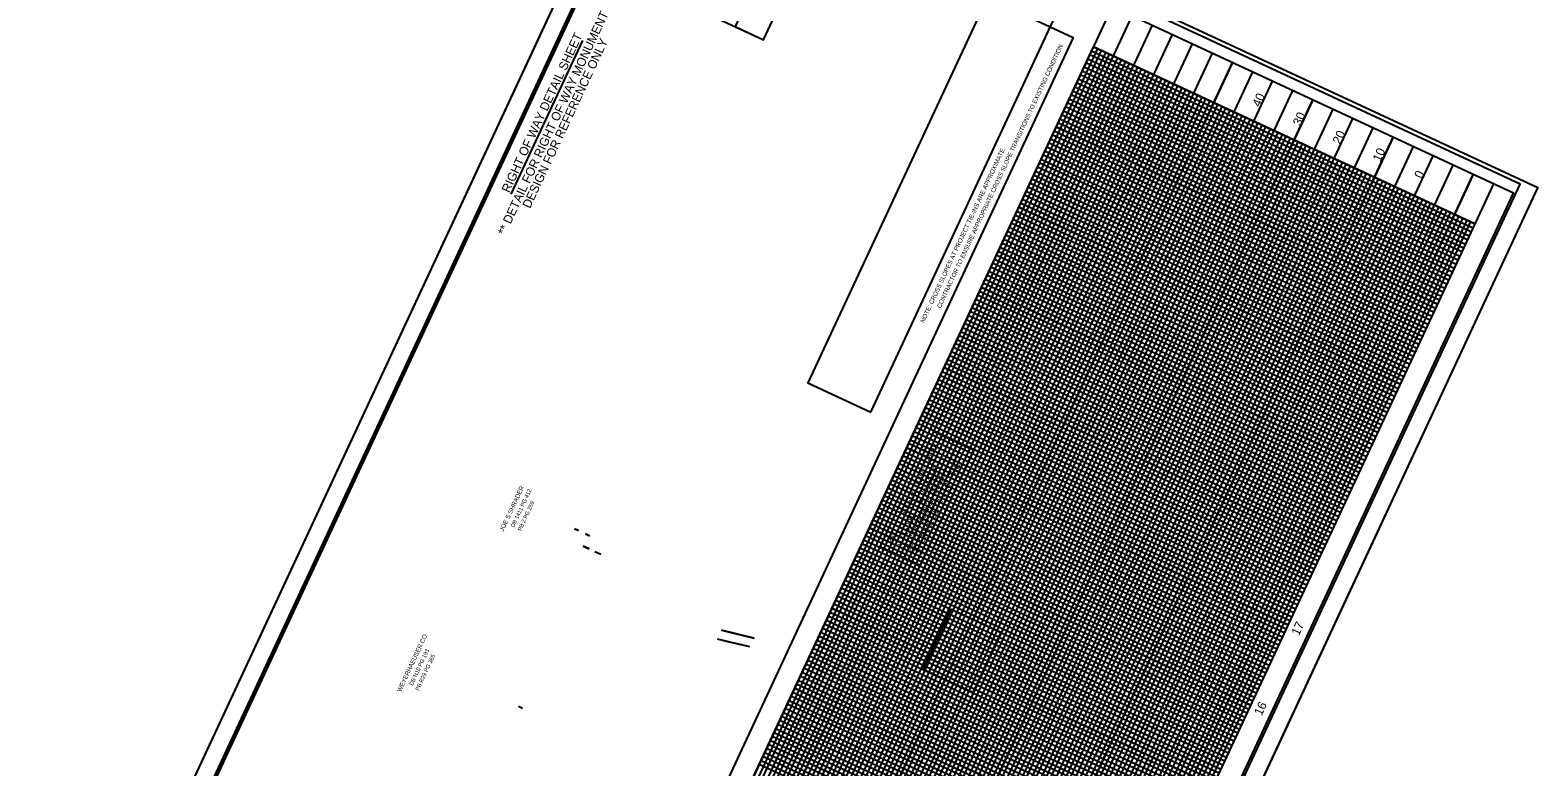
# Model space of a CAD drawing. Extents: x 2532214 to 2533961, y 714631 to 717266.
# Drawn here: x 2532214 to 2533917, y 715503 to 716336 of the extents above; entities that cross this region are included whole.
import ezdxf

# ---------------------------------------------------------------- set-up
doc = ezdxf.new("R2010")
doc.units = 0
for name, color, linetype in [('Default', 7, 'Continuous'), ('Exist Vertical Profile Horizontal Axis Label Major', 7, 'Continuous'), ('Exist Vertical Profile Vertical Axis Label', 7, 'Continuous'), ('Old_Level_1', 7, 'Continuous'), ('Prop Dimension Text', 7, 'Continuous'), ('Raster_Level_0', 7, 'Continuous'), ('Scratch_Level_0', 7, 'Continuous'), ('Scratch_Level_3', 7, 'Continuous'), ('Sheet Cutting Line CELL', 7, 'Continuous'), ('Sheet Data Field CELL', 7, 'Continuous'), ('Sheet DOT Grid CELL', 7, 'Continuous'), ('Sheet Layout Plan Border', 7, 'Continuous'), ('Sheet Plan And Profile CELL', 7, 'Continuous'), ('Sheet Plot Border Inside CELL', 7, 'Continuous'), ('Sheet Plot Border Outside CELL', 7, 'Continuous'), ('Sheet Profile Grid Major CELL', 7, 'Continuous'), ('Sheet Profile Grid Middle CELL', 7, 'Continuous'), ('Sheet Profile Grid Minor CELL', 7, 'Continuous'), ('Sheet Typical CELL', 7, 'Continuous')]:
    doc.layers.add(name, color=color, linetype=linetype)

msp = doc.modelspace()

# ---------------------------------------------------------------- linework, layer by layer
at = {"layer": 'Default'}
for points in [[(2533174.3, 715751.9), (2533235, 715882.3), (2533280.2, 715861.3), (2533219.5, 715730.8)], [(2533174.3, 715751.9), (2533235, 715882.3), (2533280.2, 715861.3), (2533219.5, 715730.8)], [(2533222.8, 715613.4), (2533254.5, 715681.4), (2533310.4, 715655.4), (2533278.8, 715587.4)], [(2533222.8, 715613.4), (2533254.5, 715681.4), (2533310.4, 715655.4), (2533278.8, 715587.4)]]:
    msp.add_lwpolyline(points, close=True, dxfattribs=at)
at = {"layer": 'Old_Level_1'}
for p, q in [((2532833.6, 715770.3), (2532829.1, 715772.4)), ((2532838.9, 715752.7), (2532845.7, 715749.6)), ((2532846, 715764.5), (2532841.4, 715766.7)), ((2532994.9, 715657.6), (2533005.6, 715655.1)), ((2533005.6, 715655.1), (2533031.8, 715648.8)), ((2532990.2, 715647.8), (2533001.9, 715645)), ((2533001.9, 715645), (2533026.7, 715639.1))]:
    msp.add_line(p, q, dxfattribs=at)
at = {"layer": 'Raster_Level_0'}
for p, q in [((2532829.1, 715772.4), (2532833.6, 715770.3)), ((2532845.7, 715749.6), (2532838.9, 715752.7)), ((2532841.4, 715766.7), (2532846, 715764.5)), ((2532851.8, 715746.7), (2532858.6, 715743.6)), ((2533031.8, 715648.8), (2532994.9, 715657.6)), ((2532990.2, 715647.8), (2533026.7, 715639.1)), ((2532765.6, 715571.8), (2532770.1, 715569.6))]:
    msp.add_line(p, q, dxfattribs=at)
msp.add_lwpolyline([(2533163.7, 715904.1), (2533382.1, 716373.6), (2533311, 716406.7), (2533092.5, 715937.2)], close=True, dxfattribs=at)
at = {"layer": 'Scratch_Level_0'}
msp.add_lwpolyline([(2532325.9, 715280), (2532853.1, 716413.3), (2533042.4, 716325.3), (2533126.8, 716506.7), (2533345.5, 716404.9), (2533436.2, 716362.7), (2533229.5, 715918.4), (2532824.5, 715048)], close=True, dxfattribs=at)
at = {"layer": 'Scratch_Level_3'}
msp.add_lwpolyline([(2532824.5, 715048), (2533229.5, 715918.4), (2533415.1, 716317.4), (2533539.1, 716259.7), (2533845.8, 716117), (2533255.2, 714847.7)], close=True, dxfattribs=at)
at = {"layer": 'Sheet Cutting Line CELL'}
for p, q in [((2532924.3, 716619.6), (2532214.1, 715093.2)), ((2533206.9, 714631.3), (2533917.1, 716157.7))]:
    msp.add_line(p, q, dxfattribs=at)
at = {"layer": 'Sheet Data Field CELL'}
msp.add_line((2532757.5, 716150.5), (2532838.3, 716324.3), dxfattribs=at)
at = {"layer": 'Sheet DOT Grid CELL'}
for p, q in [((2532939.4, 714939.4), (2533572.2, 716299.4)), ((2532848.8, 714981.6), (2533460.4, 716296.3)), ((2532894.1, 714960.5), (2533505.8, 716275.2)), ((2532984.8, 714918.3), (2533617.5, 716278.3)), ((2533394, 716272), (2533824.7, 716071.7)), ((2533030.1, 714897.2), (2533662.9, 716257.2)), ((2533075.4, 714876.1), (2533708.2, 716236.2)), ((2533120.8, 714855), (2533753.5, 716215.1)), ((2533372.9, 716226.7), (2533803.6, 716026.3)), ((2533166.1, 714834), (2533798.9, 716194)), ((2533351.8, 716181.4), (2533782.5, 715981)), ((2533211.4, 714812.9), (2533844.2, 716172.9)), ((2533330.7, 716136), (2533761.4, 715935.7)), ((2533309.6, 716090.7), (2533740.3, 715890.3)), ((2533288.5, 716045.4), (2533719.2, 715845)), ((2533267.5, 716000), (2533698.1, 715799.7)), ((2533246.4, 715954.7), (2533677, 715754.3)), ((2533225.3, 715909.4), (2533655.9, 715709)), ((2533204.2, 715864), (2533634.8, 715663.7)), ((2533183.1, 715818.7), (2533613.8, 715618.3)), ((2533162, 715773.4), (2533592.7, 715573)), ((2533140.9, 715728), (2533571.6, 715527.7)), ((2533119.8, 715682.7), (2533550.5, 715482.3)), ((2533098.7, 715637.4), (2533529.4, 715437)), ((2533077.6, 715592), (2533508.3, 715391.7)), ((2533056.5, 715546.7), (2533487.2, 715346.3))]:
    msp.add_line(p, q, dxfattribs=at)
at = {"layer": 'Sheet Layout Plan Border'}
msp.add_lwpolyline([(2532801.9, 715058.6), (2532325.9, 715280), (2532853.1, 716413.3), (2533042.4, 716325.3), (2533105.7, 716461.3), (2533392.4, 716327.9)], close=True, dxfattribs=at)
at = {"layer": 'Sheet Plan And Profile CELL'}
for p, q in [((2533436.2, 716362.7), (2532803.4, 715002.7)), ((2533866.9, 716162.3), (2533234.1, 714802.3))]:
    msp.add_line(p, q, dxfattribs=at)
msp.add_lwpolyline([(2532937.5, 716594.7), (2532304.8, 715234.7), (2533256.8, 714791.8), (2533889.5, 716151.8)], close=True, dxfattribs=at)
at = {"layer": 'Sheet Plot Border Inside CELL'}
msp.add_lwpolyline([(2533194.3, 714651.5), (2533897.1, 716162.1), (2532940.5, 716607.1), (2532237.8, 715096.6)], close=True, dxfattribs=at)
at = {"layer": 'Sheet Plot Border Outside CELL'}
msp.add_lwpolyline([(2533206.9, 714631.3), (2533917.1, 716157.7), (2532924.3, 716619.6), (2532214.1, 715093.2)], close=True, dxfattribs=at)
at = {"layer": 'Sheet Profile Grid Major CELL'}
for p, q in [((2533481.5, 716341.6), (2532848.8, 714981.6)), ((2532894.1, 714960.5), (2533526.9, 716320.5)), ((2533845.8, 716117), (2533415.1, 716317.4)), ((2533572.2, 716299.4), (2532939.4, 714939.4)), ((2532984.8, 714918.3), (2533617.5, 716278.3)), ((2533394, 716272), (2533824.7, 716071.7)), ((2533662.9, 716257.2), (2533030.1, 714897.2)), ((2533075.4, 714876.1), (2533708.2, 716236.2)), ((2533753.5, 716215.1), (2533120.8, 714855)), ((2533803.6, 716026.3), (2533372.9, 716226.7)), ((2533166.1, 714834), (2533798.9, 716194)), ((2533351.8, 716181.4), (2533782.5, 715981)), ((2533844.2, 716172.9), (2533211.4, 714812.9)), ((2533761.4, 715935.7), (2533330.7, 716136)), ((2533309.6, 716090.7), (2533740.3, 715890.3)), ((2533719.2, 715845), (2533288.5, 716045.4)), ((2533267.5, 716000), (2533698.1, 715799.7)), ((2533677, 715754.3), (2533246.4, 715954.7)), ((2533225.3, 715909.4), (2533655.9, 715709)), ((2533634.8, 715663.7), (2533204.2, 715864)), ((2533183.1, 715818.7), (2533613.8, 715618.3)), ((2533592.7, 715573), (2533162, 715773.4)), ((2533140.9, 715728), (2533571.6, 715527.7)), ((2533550.5, 715482.3), (2533119.8, 715682.7)), ((2533098.7, 715637.4), (2533529.4, 715437)), ((2533508.3, 715391.7), (2533077.6, 715592)), ((2533056.5, 715546.7), (2533487.2, 715346.3))]:
    msp.add_line(p, q, dxfattribs=at)
at = {"layer": 'Sheet Profile Grid Middle CELL'}
for p, q in [((2532826.1, 714992.1), (2533458.9, 716352.2)), ((2533504.2, 716331.1), (2532871.4, 714971.1)), ((2532916.8, 714950), (2533549.5, 716310)), ((2533594.9, 716288.9), (2532962.1, 714928.9)), ((2533404.5, 716294.7), (2533835.2, 716094.3)), ((2533007.4, 714907.8), (2533640.2, 716267.8)), ((2533685.5, 716246.7), (2533052.8, 714886.7)), ((2533814.1, 716049), (2533383.5, 716249.4)), ((2533098.1, 714865.6), (2533730.9, 716225.6)), ((2533776.2, 716204.5), (2533143.4, 714844.5)), ((2533362.4, 716204), (2533793, 716003.7)), ((2533188.8, 714823.4), (2533821.5, 716183.4)), ((2533771.9, 715958.3), (2533341.3, 716158.7)), ((2533320.2, 716113.4), (2533750.9, 715913)), ((2533729.8, 715867.7), (2533299.1, 716068)), ((2533278, 716022.7), (2533708.7, 715822.3)), ((2533687.6, 715777), (2533256.9, 715977.4)), ((2533235.8, 715932), (2533666.5, 715731.7)), ((2533645.4, 715686.3), (2533214.7, 715886.7)), ((2533193.6, 715841.4), (2533624.3, 715641)), ((2533603.2, 715595.7), (2533172.5, 715796)), ((2533151.5, 715750.7), (2533582.1, 715550.3)), ((2533561, 715505), (2533130.4, 715705.4)), ((2533109.3, 715660), (2533539.9, 715459.7)), ((2533518.8, 715414.3), (2533088.2, 715614.7)), ((2533067.1, 715569.4), (2533497.8, 715369)), ((2533476.7, 715323.7), (2533046, 715524))]:
    msp.add_line(p, q, dxfattribs=at)
at = {"layer": 'Sheet Profile Grid Minor CELL'}
for p, q in [((2533419.6, 716315.3), (2532829.1, 715045.9)), ((2532833.6, 715043.8), (2533424.2, 716313.2)), ((2533428.7, 716311), (2532838.1, 715041.7)), ((2532842.7, 715039.6), (2533433.2, 716308.9)), ((2533442.3, 716304.7), (2532851.7, 715035.4)), ((2532856.3, 715033.3), (2533446.8, 716302.6)), ((2533451.4, 716300.5), (2532860.8, 715031.1)), ((2532865.3, 715029), (2533455.9, 716298.4)), ((2533837.3, 716098.9), (2533406.7, 716299.2)), ((2533408.8, 716303.8), (2533839.4, 716103.4)), ((2533841.5, 716107.9), (2533410.9, 716308.3)), ((2533413, 716312.8), (2533843.7, 716112.5)), ((2533465, 716294.2), (2532874.4, 715024.8)), ((2532878.9, 715022.7), (2533469.5, 716292.1)), ((2533474, 716289.9), (2532883.5, 715020.6)), ((2532888, 715018.5), (2533478.6, 716287.8)), ((2533487.6, 716283.6), (2532897.1, 715014.3)), ((2532901.6, 715012.2), (2533492.2, 716281.5)), ((2533398.2, 716281.1), (2533828.9, 716080.7)), ((2533831, 716085.3), (2533400.3, 716285.6)), ((2533402.4, 716290.2), (2533833.1, 716089.8)), ((2533496.7, 716279.4), (2532906.1, 715010.1)), ((2532910.7, 715007.9), (2533501.2, 716277.3)), ((2532919.7, 715003.7), (2533510.3, 716273.1)), ((2533514.8, 716271), (2532924.3, 715001.6)), ((2532928.8, 714999.5), (2533519.4, 716268.9)), ((2533523.9, 716266.7), (2532933.3, 714997.4)), ((2533391.9, 716267.5), (2533822.6, 716067.1)), ((2533826.8, 716076.2), (2533396.1, 716276.6)), ((2532942.4, 714993.2), (2533533, 716262.5)), ((2533537.5, 716260.4), (2532946.9, 714991.1)), ((2532951.5, 714989), (2533542, 716258.3)), ((2533546.6, 716256.2), (2532956, 714986.9)), ((2532965.1, 714982.6), (2533555.6, 716252)), ((2533560.2, 716249.9), (2532969.6, 714980.5)), ((2532974.1, 714978.4), (2533564.7, 716247.8)), ((2533816.2, 716053.5), (2533385.6, 716253.9)), ((2533387.7, 716258.4), (2533818.3, 716058.1)), ((2533820.5, 716062.6), (2533389.8, 716263)), ((2533569.2, 716245.7), (2532978.7, 714976.3)), ((2532987.7, 714972.1), (2533578.3, 716241.4)), ((2533582.8, 716239.3), (2532992.3, 714970)), ((2532996.8, 714967.9), (2533587.4, 716237.2)), ((2533591.9, 716235.1), (2533001.3, 714965.8)), ((2533010.4, 714961.5), (2533601, 716230.9)), ((2533805.7, 716030.9), (2533375, 716231.2)), ((2533377.1, 716235.8), (2533807.8, 716035.4)), ((2533809.9, 716039.9), (2533379.2, 716240.3)), ((2533381.3, 716244.8), (2533812, 716044.5)), ((2533605.5, 716228.8), (2533014.9, 714959.4)), ((2533019.5, 714957.3), (2533610, 716226.7)), ((2533614.6, 716224.6), (2533024, 714955.2)), ((2533033.1, 714951), (2533623.6, 716220.3)), ((2533628.2, 716218.2), (2533037.6, 714948.9)), ((2533042.1, 714946.8), (2533632.7, 716216.1)), ((2533637.2, 716214), (2533046.7, 714944.7)), ((2533366.6, 716213.1), (2533797.3, 716012.7)), ((2533799.4, 716017.3), (2533368.7, 716217.6)), ((2533370.8, 716222.2), (2533801.5, 716021.8)), ((2533055.7, 714940.5), (2533646.3, 716209.8)), ((2533650.8, 716207.7), (2533060.3, 714938.3)), ((2533064.8, 714936.2), (2533655.4, 716205.6)), ((2533659.9, 716203.5), (2533069.3, 714934.1)), ((2533078.4, 714929.9), (2533669, 716199.3)), ((2533673.5, 716197.1), (2533082.9, 714927.8)), ((2533360.3, 716199.5), (2533790.9, 715999.1)), ((2533795.1, 716008.2), (2533364.5, 716208.6)), ((2533087.5, 714925.7), (2533678, 716195)), ((2533682.6, 716192.9), (2533092, 714923.6)), ((2533101.1, 714919.4), (2533691.6, 716188.7)), ((2533696.2, 716186.6), (2533105.6, 714917.3)), ((2533110.1, 714915.1), (2533700.7, 716184.5)), ((2533705.2, 716182.4), (2533114.7, 714913)), ((2533784.6, 715985.5), (2533353.9, 716185.9)), ((2533356, 716190.4), (2533786.7, 715990.1)), ((2533788.8, 715994.6), (2533358.1, 716195)), ((2533123.7, 714908.8), (2533714.3, 716178.2)), ((2533718.8, 716176.1), (2533128.3, 714906.7)), ((2533132.8, 714904.6), (2533723.4, 716173.9)), ((2533727.9, 716171.8), (2533137.3, 714902.5)), ((2533146.4, 714898.3), (2533737, 716167.6)), ((2533741.5, 716165.5), (2533150.9, 714896.2)), ((2533155.5, 714894.1), (2533746, 716163.4)), ((2533774.1, 715962.9), (2533343.4, 716163.2)), ((2533345.5, 716167.8), (2533776.2, 715967.4)), ((2533778.3, 715971.9), (2533347.6, 716172.3)), ((2533349.7, 716176.8), (2533780.4, 715976.5)), ((2533750.6, 716161.3), (2533160, 714891.9)), ((2533169.1, 714887.7), (2533759.6, 716157.1)), ((2533764.2, 716155), (2533173.6, 714885.6)), ((2533178.1, 714883.5), (2533768.7, 716152.9)), ((2533773.2, 716150.7), (2533182.7, 714881.4)), ((2533191.7, 714877.2), (2533782.3, 716146.5)), ((2533196.3, 714875.1), (2533786.8, 716144.4)), ((2533334.9, 716145.1), (2533765.6, 715944.7)), ((2533767.7, 715949.3), (2533337.1, 716149.6)), ((2533339.2, 716154.2), (2533769.8, 715953.8)), ((2533791.4, 716142.3), (2533200.8, 714873)), ((2533205.3, 714870.9), (2533795.9, 716140.2)), ((2533805, 716136), (2533214.4, 714866.6)), ((2533218.9, 714864.5), (2533809.5, 716133.9)), ((2533814, 716131.8), (2533223.5, 714862.4)), ((2533228, 714860.3), (2533818.6, 716129.7)), ((2533328.6, 716131.5), (2533759.3, 715931.1)), ((2533763.5, 715940.2), (2533332.8, 716140.6)), ((2533827.6, 716125.4), (2533237.1, 714856.1)), ((2533241.6, 714854), (2533832.2, 716123.3)), ((2533836.7, 716121.2), (2533246.1, 714851.9)), ((2533250.7, 714849.8), (2533841.2, 716119.1)), ((2533753, 715917.5), (2533322.3, 716117.9)), ((2533324.4, 716122.4), (2533755.1, 715922.1)), ((2533757.2, 715926.6), (2533326.5, 716127)), ((2533742.4, 715894.9), (2533311.7, 716095.2)), ((2533313.9, 716099.8), (2533744.5, 715899.4)), ((2533746.6, 715903.9), (2533316, 716104.3)), ((2533318.1, 716108.8), (2533748.7, 715908.5)), ((2533303.3, 716077.1), (2533734, 715876.7)), ((2533736.1, 715881.3), (2533305.4, 716081.6)), ((2533307.5, 716086.2), (2533738.2, 715885.8)), ((2533297, 716063.5), (2533727.7, 715863.1)), ((2533731.9, 715872.2), (2533301.2, 716072.6)), ((2533721.3, 715849.5), (2533290.7, 716049.9)), ((2533292.8, 716054.4), (2533723.4, 715854.1)), ((2533725.5, 715858.6), (2533294.9, 716059)), ((2533710.8, 715826.9), (2533280.1, 716027.2)), ((2533282.2, 716031.8), (2533712.9, 715831.4)), ((2533715, 715835.9), (2533284.3, 716036.3)), ((2533286.4, 716040.8), (2533717.1, 715840.5)), ((2533271.7, 716009.1), (2533702.3, 715808.7)), ((2533704.5, 715813.3), (2533273.8, 716013.6)), ((2533275.9, 716018.2), (2533706.6, 715817.8)), ((2533265.3, 715995.5), (2533696, 715795.1)), ((2533700.2, 715804.2), (2533269.6, 716004.6)), ((2533689.7, 715781.5), (2533259, 715981.9)), ((2533261.1, 715986.4), (2533691.8, 715786.1)), ((2533693.9, 715790.6), (2533263.2, 715991)), ((2533679.1, 715758.9), (2533248.5, 715959.2)), ((2533250.6, 715963.8), (2533681.3, 715763.4)), ((2533683.4, 715767.9), (2533252.7, 715968.3)), ((2533254.8, 715972.8), (2533685.5, 715772.5)), ((2533240, 715941.1), (2533670.7, 715740.7)), ((2533672.8, 715745.3), (2533242.1, 715945.6)), ((2533244.3, 715950.2), (2533674.9, 715749.8)), ((2533662.3, 715722.6), (2533231.6, 715923)), ((2533233.7, 715927.5), (2533664.4, 715727.1)), ((2533668.6, 715736.2), (2533237.9, 715936.6)), ((2533658.1, 715713.5), (2533227.4, 715913.9)), ((2533229.5, 715918.4), (2533660.2, 715718.1)), ((2533647.5, 715690.9), (2533216.8, 715891.2)), ((2533218.9, 715895.8), (2533649.6, 715695.4)), ((2533651.7, 715699.9), (2533221.1, 715900.3)), ((2533223.2, 715904.8), (2533653.8, 715704.5)), ((2533208.4, 715873.1), (2533639.1, 715672.7)), ((2533641.2, 715677.3), (2533210.5, 715877.6)), ((2533212.6, 715882.2), (2533643.3, 715681.8)), ((2533630.6, 715654.6), (2533200, 715855)), ((2533202.1, 715859.5), (2533632.7, 715659.1)), ((2533637, 715668.2), (2533206.3, 715868.6)), ((2533626.4, 715645.5), (2533195.7, 715845.9)), ((2533197.9, 715850.4), (2533628.5, 715650.1)), ((2533615.9, 715622.9), (2533185.2, 715823.2)), ((2533187.3, 715827.8), (2533618, 715627.4)), ((2533620.1, 715631.9), (2533189.4, 715832.3)), ((2533191.5, 715836.8), (2533622.2, 715636.5)), ((2533176.8, 715805.1), (2533607.4, 715604.7)), ((2533609.5, 715609.3), (2533178.9, 715809.6)), ((2533181, 715814.2), (2533611.6, 715613.8)), ((2533599, 715586.6), (2533168.3, 715787)), ((2533170.4, 715791.5), (2533601.1, 715591.1)), ((2533605.3, 715600.2), (2533174.7, 715800.6)), ((2533594.8, 715577.5), (2533164.1, 715777.9)), ((2533166.2, 715782.4), (2533596.9, 715582.1)), ((2533584.2, 715554.9), (2533153.6, 715755.2)), ((2533155.7, 715759.8), (2533586.3, 715559.4)), ((2533588.4, 715563.9), (2533157.8, 715764.3)), ((2533159.9, 715768.8), (2533590.6, 715568.5)), ((2533145.1, 715737.1), (2533575.8, 715536.7)), ((2533577.9, 715541.3), (2533147.2, 715741.6)), ((2533149.3, 715746.2), (2533580, 715545.8)), ((2533567.4, 715518.6), (2533136.7, 715719)), ((2533138.8, 715723.5), (2533569.5, 715523.1)), ((2533573.7, 715532.2), (2533143, 715732.6)), ((2533563.1, 715509.5), (2533132.5, 715709.9)), ((2533134.6, 715714.4), (2533565.2, 715514.1)), ((2533552.6, 715486.9), (2533121.9, 715687.2)), ((2533124, 715691.8), (2533554.7, 715491.4)), ((2533556.8, 715495.9), (2533126.1, 715696.3)), ((2533128.2, 715700.8), (2533558.9, 715500.5)), ((2533113.5, 715669.1), (2533544.2, 715468.7)), ((2533546.3, 715473.3), (2533115.6, 715673.6)), ((2533117.7, 715678.2), (2533548.4, 715477.8)), ((2533535.7, 715450.6), (2533105, 715651)), ((2533107.2, 715655.5), (2533537.8, 715455.1)), ((2533542, 715464.2), (2533111.4, 715664.6)), ((2533531.5, 715441.5), (2533100.8, 715641.9)), ((2533102.9, 715646.4), (2533533.6, 715446.1)), ((2533521, 715418.9), (2533090.3, 715619.2)), ((2533092.4, 715623.8), (2533523.1, 715423.4)), ((2533525.2, 715427.9), (2533094.5, 715628.3)), ((2533096.6, 715632.8), (2533527.3, 715432.5)), ((2533081.8, 715601.1), (2533512.5, 715400.7)), ((2533514.6, 715405.3), (2533084, 715605.6)), ((2533086.1, 715610.2), (2533516.7, 715409.8)), ((2533504.1, 715382.6), (2533073.4, 715583)), ((2533075.5, 715587.5), (2533506.2, 715387.1)), ((2533510.4, 715396.2), (2533079.7, 715596.6)), ((2533499.9, 715373.5), (2533069.2, 715573.9)), ((2533071.3, 715578.4), (2533502, 715378.1)), ((2533489.3, 715350.9), (2533058.6, 715551.2)), ((2533060.8, 715555.8), (2533491.4, 715355.4)), ((2533493.5, 715359.9), (2533062.9, 715560.3)), ((2533065, 715564.8), (2533495.6, 715364.5)), ((2533050.2, 715533.1), (2533480.9, 715332.7)), ((2533483, 715337.3), (2533052.3, 715537.6)), ((2533054.4, 715542.2), (2533485.1, 715341.8)), ((2533472.4, 715314.6), (2533041.8, 715515)), ((2533043.9, 715519.5), (2533474.6, 715319.1)), ((2533478.8, 715328.2), (2533048.1, 715528.6)), ((2533468.2, 715305.5), (2533037.6, 715505.9)), ((2533039.7, 715510.4), (2533470.3, 715310.1))]:
    msp.add_line(p, q, dxfattribs=at)
at = {"layer": 'Sheet Typical CELL'}
msp.add_lwpolyline([(2533094.9, 716521.5), (2533010.5, 716340.1), (2533042.4, 716325.3), (2533126.8, 716506.6)], close=True, dxfattribs=at)

# ---------------------------------------------------------------- texts
at = {"layer": 'Default'}
for s, height, p in [('BM1       ELEVATION = 24.93', 7, (2533188.1, 715754.3)), ('N 715991      E 2533024', 7, (2533197.6, 715749.8)), ('RR SPIKE SET IN 18" PINE', 7, (2533216.6, 715741)), ('BL STATION 32+22.00', 7, (2533207.1, 715745.4)), ('JOE S SHRADER', 5, (2532748.7, 715768.9)), ('DB 1411 PG 412', 4.5, (2532760.8, 715773.4)), ('PB 2 PG 259', 4.5, (2532768.6, 715769.4)), ('WEYERHAEUSER CO', 5, (2532632.9, 715587.4)), ('DB N10 PG 193', 4.5, (2532646.2, 715594.7)), ('PB R29 PG 365', 4.5, (2532653.1, 715588.9))]:
    msp.add_text(s, height=height, rotation=65.05, dxfattribs=at).set_placement(p)
at = {"layer": 'Exist Vertical Profile Horizontal Axis Label Major'}
for s, p in [('17', (2533647.2, 715650.8)), ('16', (2533605.1, 715560.3))]:
    msp.add_text(s, height=10, rotation=65.05, dxfattribs=at).set_placement(p)
at = {"layer": 'Exist Vertical Profile Vertical Axis Label'}
for s, p in [('40', (2533603, 716248.4)), ('30', (2533648.9, 716227)), ('20', (2533693.7, 716206.2)), ('10', (2533739, 716186.4)), ('0', (2533786, 716167.6))]:
    msp.add_text(s, height=10, rotation=65.05, dxfattribs=at).set_placement(p)
at = {"layer": 'Prop Dimension Text'}
for s, p in [('            CONTRACTOR TO ENSURE APPROPRIATE CROSS SLOPE TRANSITIONS TO EXISTING CONDITION', (2533232.9, 716000.4)), ('NOTE: CROSS SLOPES AT PROJECT TIE-INS ARE APPROXIMATE.', (2533223.9, 716004.7))]:
    msp.add_text(s, height=5, rotation=65.05, dxfattribs=at).set_placement(p)
at = {"layer": 'Sheet Data Field CELL'}
for s, p in [('** DETAIL FOR RIGHT OF WAY MONUMENT', (2532750.8, 716103.4)), ('RIGHT OF WAY DETAIL SHEET', (2532755.2, 716151.5)), ('DESIGN FOR REFERENCE ONLY', (2532778.7, 716133.8))]:
    msp.add_text(s, height=10, rotation=65.05, dxfattribs=at).set_placement(p)

doc.saveas('drawing.dxf')
